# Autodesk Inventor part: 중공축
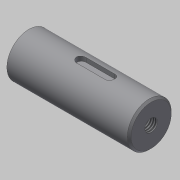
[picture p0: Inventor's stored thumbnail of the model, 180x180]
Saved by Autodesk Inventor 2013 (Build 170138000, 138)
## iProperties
Created: 2019-10
Part Number: 중공축
Material: 강철, 탄소
Document SubType Name: Modeling
Designer: mduedu
Density: 1 g/cm^3
Author: mduedu
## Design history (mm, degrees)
sketch "스케치1"
  geometry: L1 (0, 0)-(64, 0); L2 (64, 0)-(64, 11.5); L3 (64, 11.5)-(0, 11.5); L4 (0, 11.5)-(0, 0)
  constraints: 8 end point, 2 parallel, 1 horizontal, 1 perpendicular
  dimensions: "d0" = 64 distance of L2.end L3.end; "d2" = 23 diameter of L3 L1
revolve "회전1" sketch "스케치1" stored, may be unused: angle "d3" = 90 deg
hole "구멍1" diameter "d6" = 6.647; stored, may be unused: countersink angle "d10" = 90 deg, drill point angle "d12" = 118 deg; dims "d4" = 10, "d5" = 10, "d7" = 6, "d8" = 4, "d9" = 2, "d11" = 8
hole "구멍2" diameter "d15" = 13; stored, may be unused: countersink angle "d19" = 90 deg, drill point angle "d21" = 0 deg; dims "d13" = 10, "d14" = 10, "d16" = 6, "d17" = 15, "d18" = 20, "d20" = 32
sketch "스케치2"
  geometry: L1 (20, -7.5)-(20, -6.5) reference; L2 (20, -6.5)-(52, -6.5) reference; L3 (52, -6.5)-(52, -3.324) reference; L4 (52, -3.324)-(64, -3.324) reference; L5 (64, -3.324)-(64, -11.5) reference; L6 (64, -11.5)-(0, -11.5) reference; L7 (0, -11.5)-(0, -7.5) reference; L8 (0, -7.5)-(20, -7.5) reference; L9 (20, 6.5)-(20, 7.5) reference; L10 (20, 7.5)-(0, 7.5) reference; L11 (0, 7.5)-(0, 11.5) reference; L12 (0, 11.5)-(64, 11.5) reference; L13 (64, 11.5)-(64, 3.324) reference; L14 (64, 3.324)-(52, 3.324) reference; L15 (52, 3.324)-(52, 6.5) reference; L16 (52, 6.5)-(20, 6.5) reference; L17 (25, 11.5)-(45, 11.5); L18 (45, 11.5)-(45, 9); L19 (45, 9)-(25, 9); L20 (25, 9)-(25, 11.5); 1 further point
  constraints: 8 end point, 2 parallel, 1 horizontal, 1 perpendicular, 1 point on line
  dimensions: "d22" = 20 distance of L17.start L17.end; "d24" = 25 distance between parallel lines of L20 L11; "d25" = 2.5 distance of L17.end L18.end
extrude "돌출1" cut sketch "스케치2" stored distance "d26" = 5; taper "d27" = 0 deg
fillet "모깎기1"
fillet "모깎기2"
sketch "스케치3"
  geometry: 3 further points
  constraints: 2 vertical alignment, 1 other
hole "구멍3" sketch "스케치3" at (0, 7.5) diameter "d28" = 2.459; stored, may be unused: countersink angle "d32" = 90 deg, drill point angle "d34" = 118 deg; dims "d29" = 6, "d30" = 4, "d31" = 2, "d33" = 8
chamfer "모따기1" distance "d35" = 1; stored, may be unused: second distance "d36" = 2, angle "d37" = 45 deg
node "솔리드1"
node "절단 모서리 투영1"
